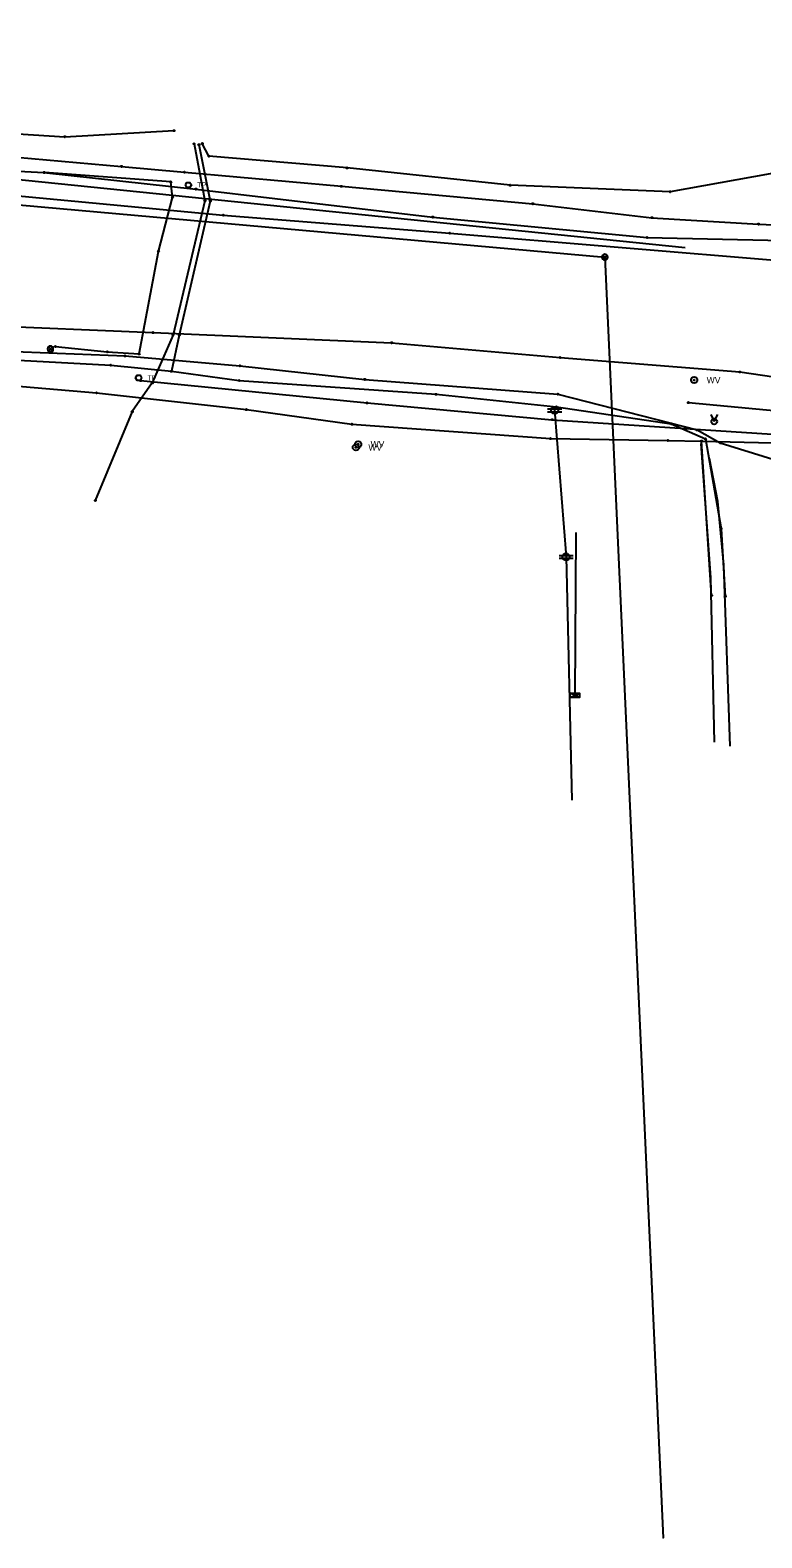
# Model space of a CAD drawing. Extents: x 20500343 to 20505311, y 7953484 to 7954193.
# Drawn here: x 20500764 to 20500991.2, y 7953579.5 to 7954047.5 of the extents above; entities that cross this region are included whole.
import ezdxf

# ---------------------------------------------------------------- set-up
doc = ezdxf.new("R2010")
doc.units = 0
for name, color, linetype in [('C-PROP-LINE-LOT', 7, 'Continuous'), ('V-ANNO-NOTE', 7, 'Continuous'), ('V-CTRL-HVPT', 7, 'Continuous'), ('V-MON-FND', 7, 'Continuous'), ('V-SSWR-STRC', 7, 'Continuous'), ('VF-NODE-MISC', 7, 'Continuous')]:
    doc.layers.add(name, color=color, linetype=linetype)

msp = doc.modelspace()

# ---------------------------------------------------------------- linework, layer by layer
at = {"layer": 'C-PROP-LINE-LOT'}
for points in [[(20500406.13, 7954047.52), (20500473.69, 7954042.07), (20500666.63, 7954023.16), (20500691.11, 7954020.37), (20500735.76, 7954016.9), (20500774.72, 7954014.43), (20500808.62, 7954016.33)], [(20500406.47, 7954039.57), (20500466.05, 7954034.11), (20500535.84, 7954027.4), (20500662.16, 7954017.11), (20500704.07, 7954013.07), (20500745.63, 7954009.37), (20500792.32, 7954005.22), (20500811.87, 7954003.45), (20500860.59, 7953999.05), (20500920.01, 7953993.63), (20500957.01, 7953989.31), (20500990.1, 7953987.34), (20501028.58, 7953985.6), (20501071.83, 7953984.74), (20501141.27, 7953979.76), (20501204.8, 7953974.46), (20501273.24, 7953968.85)], [(20500408.85, 7954033.69), (20500534.28, 7954022.2), (20500733.06, 7954003.91), (20500967.33, 7953980.02)], [(20500343.29, 7954030.83), (20500591.11, 7954008.44), (20500942.44, 7953977.04), (20500960.49, 7953579.51)], [(20500542.46, 7954022.99), (20500657.16, 7954010.94), (20500703.46, 7954006.71), (20500768.23, 7954003.33), (20500815.45, 7953998.2), (20500888.96, 7953989.5), (20500955.53, 7953983.16), (20501072.58, 7953980.59), (20501105.36, 7953988.74)], [(20500542.46, 7954013.94), (20500614.61, 7954008.93), (20500657.56, 7954005.52), (20500702.03, 7954001.63), (20500823.93, 7953990.08), (20500894.24, 7953984.51), (20500998.83, 7953975.83), (20501086.53, 7953973.45), (20501164.96, 7953976.11), (20501261.79, 7953980.89), (20501339.33, 7953977.27), (20501419.74, 7953970.03), (20501525.89, 7953965.34), (20501551.15, 7953963.49), (20501624.16, 7953957.55)], [(20500814.84, 7954012.24), (20500818.23, 7953994.57), (20500808.34, 7953952.99), (20500801.89, 7953938.02), (20500795.67, 7953929.1), (20500784.19, 7953901.52)], [(20500816.37, 7954011.98), (20500819.88, 7953994.46), (20500810.28, 7953952.88), (20500807.81, 7953941.62)], [(20501305.59, 7953998.76), (20501259.79, 7953998.97), (20501211.09, 7953999.57), (20501118.97, 7954006.88), (20501070.28, 7954009.47), (20501014.48, 7954006.68), (20500962.69, 7953997.37), (20500913.01, 7953999.39), (20500862.37, 7954004.75), (20500819.48, 7954008.4), (20500817.42, 7954012.31)], [(20500771.81, 7953949.32), (20500787.91, 7953947.68), (20500797.78, 7953947), (20500803.81, 7953978.84), (20500808.16, 7953995.6), (20500807.64, 7954000.4), (20500768.42, 7954003.35)], [(20500520.98, 7953977.28), (20500560.2, 7953972.18), (20500580.11, 7953968.09), (20500618.43, 7953964.47), (20500633.81, 7953963.45), (20500668.21, 7953960.34), (20500693.49, 7953957.8), (20500747.72, 7953955.96), (20500802.14, 7953953.65), (20500876.21, 7953950.48), (20500928.48, 7953945.92), (20500984.31, 7953941.41), (20501068.76, 7953929.07), (20501169.59, 7953917.28), (20501247.95, 7953910.8), (20501285.38, 7953908.94), (20501306.14, 7953908.1), (20501320.57, 7953910.34), (20501331.41, 7953911.48)], [(20500469.9, 7953970.65), (20500505.35, 7953968.7), (20500522.37, 7953967.11), (20500565.63, 7953966.99), (20500619.43, 7953961.41), (20500633.65, 7953961.99), (20500668.11, 7953958.55), (20500688.24, 7953956.38), (20500722.3, 7953952.32), (20500751.12, 7953948.12), (20500793.42, 7953946.39), (20500829.09, 7953943.31), (20500867.84, 7953939.12), (20500927.83, 7953934.54), (20500971.05, 7953923.41), (20500978.23, 7953919.45), (20500994.58, 7953914.36)], [(20500542.27, 7953966.39), (20500567.09, 7953964.35), (20500611.73, 7953958.49), (20500625.61, 7953958.17), (20500630.34, 7953957.23), (20500641.04, 7953945.21), (20500677.24, 7953941.24), (20500710.61, 7953939.53), (20500749.41, 7953937.97), (20500784.55, 7953934.93), (20500831.09, 7953929.74), (20500863.89, 7953925.18), (20500925.53, 7953920.74), (20500962.01, 7953920.15), (20500972.45, 7953919.98), (20500994.6, 7953919.38), (20501012.87, 7953913.32), (20501056.03, 7953910.21), (20501118.83, 7953905.26), (20501155.51, 7953903.82), (20501202, 7953902.86), (20501247.06, 7953903.19), (20501262.67, 7953902.86)], [(20500561.73, 7953900.93), (20500559.97, 7953938.39), (20500560.68, 7953946.27), (20500567.17, 7953949.77), (20500607.64, 7953952.7), (20500645.48, 7953948.64), (20500675.39, 7953949.59), (20500709.23, 7953946.92), (20500752.57, 7953945.49), (20500788.98, 7953943.53), (20500807.81, 7953941.62), (20500828.86, 7953938.77), (20500890, 7953934.48), (20500927.37, 7953930.61), (20500963.01, 7953925.35), (20500973.65, 7953920.63), (20500978.51, 7953892.75), (20500979.78, 7953871.77)], [(20500798.27, 7953938.75), (20500868.59, 7953931.82), (20500926.05, 7953926.61), (20501045.21, 7953918.84), (20501106.16, 7953923.17)], [(20500926.81, 7953929.52), (20500930.38, 7953884.02), (20500932.15, 7953808.51)], [(20500968.33, 7953931.91), (20501234.75, 7953906.92), (20501256.26, 7953906.33), (20501308.38, 7953902.25), (20501316.23, 7953902.74), (20501321.08, 7953908.26)], [(20500975.56, 7953872.03), (20500972.45, 7953919.98)], [(20500976.42, 7953826.47), (20500975.3, 7953877.61), (20500972.36, 7953919.16)], [(20500981.36, 7953825.26), (20500979.33, 7953881.58), (20500977.47, 7953901.18), (20500974.95, 7953914.61)], [(20500933.4, 7953891.6), (20500933.11, 7953841.04)]]:
    msp.add_lwpolyline(points, dxfattribs=at)
at = {"layer": 'V-ANNO-NOTE'}
for centre in [(20500774.72, 7954014.43), (20500808.62, 7954016.33), (20500814.84, 7954012.24), (20500816.37, 7954011.98), (20500817.42, 7954012.31), (20500819.48, 7954008.4), (20500768.23, 7954003.33), (20500768.42, 7954003.35), (20500792.32, 7954005.22), (20500811.87, 7954003.45), (20500862.37, 7954004.75), (20500807.64, 7954000.4), (20500860.59, 7953999.05), (20500913.01, 7953999.39), (20500808.16, 7953995.6), (20500815.45, 7953998.2), (20500818.23, 7953994.57), (20500819.88, 7953994.46), (20500962.69, 7953997.37), (20500823.93, 7953990.08), (20500888.96, 7953989.5), (20500920.01, 7953993.63), (20500957.01, 7953989.31), (20500990.1, 7953987.34), (20500894.24, 7953984.51), (20500955.53, 7953983.16), (20500803.81, 7953978.84), (20500802.14, 7953953.65), (20500808.34, 7953952.99), (20500810.28, 7953952.88), (20500771.81, 7953949.32), (20500787.91, 7953947.68), (20500876.21, 7953950.48), (20500788.98, 7953943.53), (20500793.42, 7953946.39), (20500797.78, 7953947), (20500829.09, 7953943.31), (20500928.48, 7953945.92), (20500798.27, 7953938.75), (20500801.89, 7953938.02), (20500807.81, 7953941.62), (20500807.81, 7953941.62), (20500828.86, 7953938.77), (20500867.84, 7953939.12), (20500984.31, 7953941.41), (20500784.55, 7953934.93), (20500890, 7953934.48), (20500927.83, 7953934.54), (20500795.67, 7953929.1), (20500831.09, 7953929.74), (20500868.59, 7953931.82), (20500927.37, 7953930.61), (20500968.33, 7953931.91), (20500863.89, 7953925.18), (20500926.05, 7953926.61), (20500963.01, 7953925.35), (20500925.53, 7953920.74), (20500962.01, 7953920.15), (20500971.05, 7953923.41), (20500972.45, 7953919.98), (20500972.45, 7953919.98), (20500973.65, 7953920.63), (20500978.23, 7953919.45), (20500784.19, 7953901.52), (20500978.51, 7953892.75), (20500975.56, 7953872.03), (20500979.78, 7953871.77)]:
    msp.add_circle(centre, 0.2, dxfattribs=at)
at = {"layer": 'V-CTRL-HVPT'}
for p, q in [((20500924.61, 7953929.96), (20500929.01, 7953929.96)), ((20500924.61, 7953929.08), (20500929.01, 7953929.08)), ((20500928.18, 7953884.46), (20500932.58, 7953884.46)), ((20500928.18, 7953883.58), (20500932.58, 7953883.58))]:
    msp.add_line(p, q, dxfattribs=at)
for centre in [(20500926.81, 7953929.52), (20500930.38, 7953884.02)]:
    msp.add_circle(centre, 1.1, dxfattribs=at)
at = {"layer": 'V-MON-FND'}
for points in [[(20500812.21, 7953999.49), (20500812.66, 7954000.28), (20500813.58, 7954000.28), (20500814.03, 7953999.49), (20500813.58, 7953998.7), (20500812.66, 7953998.7), (20500812.21, 7953999.49)], [(20500796.71, 7953939.61), (20500797.16, 7953940.41), (20500798.08, 7953940.41), (20500798.53, 7953939.61), (20500798.08, 7953938.82), (20500797.16, 7953938.82), (20500796.71, 7953939.61)]]:
    msp.add_lwpolyline(points, dxfattribs=at)
at = {"layer": 'V-SSWR-STRC'}
for points in [[(20500941.8, 7953976.41), (20500942.44, 7953977.04), (20500941.8, 7953977.68)], [(20500943.08, 7953977.68), (20500942.44, 7953977.04), (20500943.08, 7953976.41)], [(20500769.61, 7953947.92), (20500770.25, 7953948.56), (20500769.61, 7953949.19)], [(20500770.89, 7953949.19), (20500770.25, 7953948.56), (20500770.89, 7953947.92)], [(20500931.67, 7953840.32), (20500934.55, 7953841.76), (20500934.55, 7953840.32), (20500931.67, 7953841.76)], [(20500960.49, 7953579.51), (20500960.49, 7953579.51), (20500960.49, 7953579.51)], [(20500960.49, 7953579.51), (20500960.49, 7953579.51), (20500960.49, 7953579.51)]]:
    msp.add_lwpolyline(points, dxfattribs=at)
msp.add_lwpolyline([(20500931.67, 7953840.32), (20500931.67, 7953841.76), (20500934.55, 7953841.76), (20500934.55, 7953840.32)], close=True, dxfattribs=at)
for centre, radius in [((20500970.15, 7953938.91), 0.971), ((20500970.15, 7953938.91), 0.162), ((20500865.8, 7953918.99), 0.971), ((20500865.1, 7953917.99), 0.971), ((20500865.1, 7953917.99), 0.162), ((20500865.8, 7953918.99), 0.162)]:
    msp.add_circle(centre, radius, dxfattribs=at)
for centre, radius, start, end in [((20500942.44, 7953977.04), 0.899, 135, 225), ((20500942.44, 7953977.04), 0.899, 45, 135), ((20500942.44, 7953977.04), 0.899, 225, 315), ((20500942.44, 7953977.04), 0.899, 315, 45), ((20500770.25, 7953948.56), 0.899, 135, 225), ((20500770.25, 7953948.56), 0.899, 45, 135), ((20500770.25, 7953948.56), 0.899, 225, 315), ((20500770.25, 7953948.56), 0.899, 315, 45), ((20500960.49, 7953579.51), 0.0015, 225, 315), ((20500960.49, 7953579.51), 0.0015, 45, 135), ((20500960.49, 7953579.51), 0.0015, 135, 225), ((20500960.49, 7953579.51), 0.0015, 315, 45)]:
    msp.add_arc(centre, radius, start, end, dxfattribs=at)
at = {"layer": 'VF-NODE-MISC'}
for p, q in [((20500975.29, 7953928.21), (20500976.37, 7953926.05)), ((20500976.37, 7953926.05), (20500977.45, 7953928.21))]:
    msp.add_line(p, q, dxfattribs=at)
msp.add_circle((20500976.37, 7953926.05), 0.897, dxfattribs=at)

# ---------------------------------------------------------------- texts
at = {"layer": 'V-MON-FND'}
for p in [(20500815.86, 7953998.69), (20500800.36, 7953938.81)]:
    msp.add_text('TP', height=1.599, dxfattribs=at).set_placement(p)
at = {"layer": 'V-SSWR-STRC'}
for p in [(20500974.03, 7953937.92), (20500869.68, 7953918), (20500868.98, 7953917)]:
    msp.add_text('WV', height=1.982, dxfattribs=at).set_placement(p)

doc.saveas('drawing.dxf')
